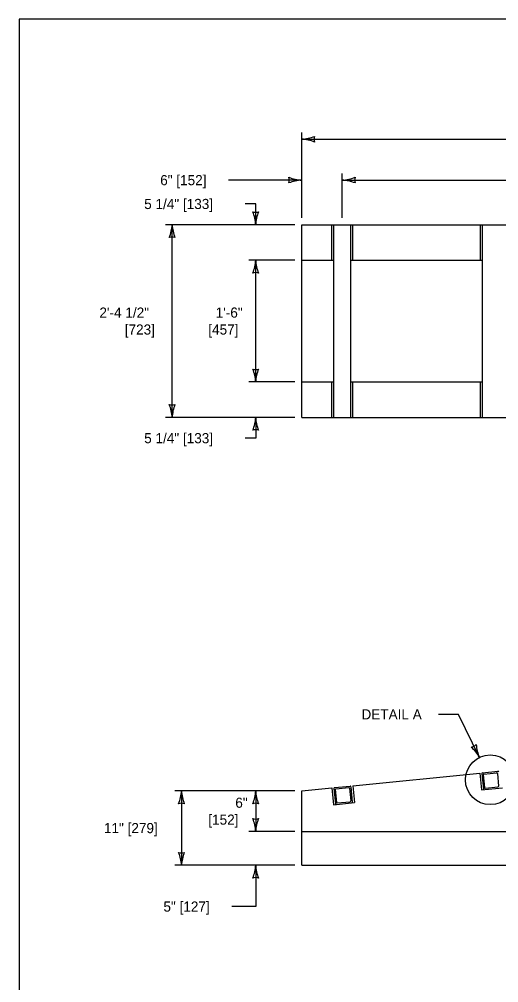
# Model space of a CAD drawing. Extents: x 49991.4 to 50021, y 49987.6 to 50011.4.
# Drawn here: x 50000.34 to 50003.17, y 50005.56 to 50011.26 of the extents above; entities that cross this region are included whole.
import ezdxf

# ---------------------------------------------------------------- set-up
doc = ezdxf.new("R2010")
doc.units = 0
for name, color, linetype in [('Level 1', 7, 'Continuous'), ('Level 2', 7, 'Continuous'), ('Level 3', 7, 'Continuous'), ('Level 4', 7, 'Continuous')]:
    doc.layers.add(name, color=color, linetype=linetype)

msp = doc.modelspace()

# ---------------------------------------------------------------- linework, layer by layer
at = {"layer": 'Level 1'}
for p, q in [((50002.0071, 50008.9073), (50002.0071, 50010.0473)), ((50002.0071, 50010.0473), (50006.5671, 50010.0473)), ((50002.1851, 50009.8374), (50002.1851, 50010.0473)), ((50002.1971, 50008.9073), (50002.1971, 50010.0473)), ((50002.2971, 50008.9073), (50002.2971, 50010.0473)), ((50002.3091, 50009.8374), (50002.3091, 50010.0473)), ((50003.0651, 50009.8374), (50003.0651, 50010.0473)), ((50003.0771, 50008.9073), (50003.0771, 50010.0473)), ((50002.0071, 50009.8374), (50002.1971, 50009.8374)), ((50002.2971, 50009.8374), (50003.0771, 50009.8374)), ((50002.0071, 50009.1174), (50002.1971, 50009.1174)), ((50002.1851, 50008.9073), (50002.1851, 50009.1174)), ((50002.2971, 50009.1174), (50003.0771, 50009.1174)), ((50002.3091, 50008.9073), (50002.3091, 50009.1174)), ((50003.0651, 50008.9073), (50003.0651, 50009.1174)), ((50002.0071, 50008.9073), (50006.5671, 50008.9073)), ((50002.3091, 50006.7277), (50003.0608, 50006.8028)), ((50003.0608, 50006.8028), (50003.0707, 50006.7032)), ((50003.0732, 50006.8), (50003.0823, 50006.7084)), ((50003.0768, 50006.8044), (50003.1688, 50006.8135)), ((50003.0812, 50006.7927), (50003.0887, 50006.7171)), ((50003.0848, 50006.7971), (50003.1608, 50006.8047)), ((50003.1652, 50006.8011), (50003.1727, 50006.7255)), ((50002.0071, 50006.6976), (50002.1851, 50006.7153)), ((50002.1851, 50006.7153), (50002.1951, 50006.6159)), ((50002.2011, 50006.7169), (50002.2932, 50006.7261)), ((50002.2091, 50006.7097), (50002.2852, 50006.7173)), ((50002.2975, 50006.7225), (50002.3066, 50006.631)), ((50002.3091, 50006.7277), (50002.3191, 50006.6282)), ((50003.0707, 50006.7032), (50003.1947, 50006.7156)), ((50003.0931, 50006.7135), (50003.1692, 50006.7211)), ((50002.0071, 50006.2576), (50002.0071, 50006.6976)), ((50002.1975, 50006.7126), (50002.2067, 50006.621)), ((50002.2055, 50006.7053), (50002.2131, 50006.6297)), ((50002.2895, 50006.7137), (50002.2971, 50006.6381)), ((50002.1951, 50006.6159), (50002.3191, 50006.6282)), ((50002.2174, 50006.6261), (50002.2935, 50006.6337)), ((50002.0071, 50006.2576), (50006.5671, 50006.2576))]:
    msp.add_line(p, q, dxfattribs=at)
msp.add_lwpolyline([(50008.6146, 50011.2628), (50000.3356, 50011.2628), (50000.3356, 50000.0624), (50008.6146, 50000.0624)], close=True, dxfattribs=at)
for centre, radius, start, end in [((50003.0772, 50006.8004), 0.00402, 95.7106, 185.7106), ((50003.0852, 50006.7931), 0.00402, 95.7106, 185.7106), ((50003.1612, 50006.8007), 0.00402, 5.7106, 95.7106), ((50003.1692, 50006.8096), 0.00398, 6.4993, 96.4993), ((50002.2015, 50006.7129), 0.00397, 95.0636, 185.0636), ((50002.2855, 50006.7133), 0.00397, 5.0636, 95.0636), ((50002.2935, 50006.7221), 0.00397, 5.0636, 95.0636), ((50003.0927, 50006.7175), 0.00402, 185.7106, 275.7106), ((50003.1687, 50006.7251), 0.00398, 276.4993, 6.4993), ((50002.2095, 50006.7057), 0.00402, 95.7106, 185.7106), ((50003.0863, 50006.7088), 0.00402, 185.9049, 275.9049), ((50002.2104, 50006.6211), 0.00368, 181.6745, 271.6745), ((50002.217, 50006.63), 0.00397, 185.0636, 275.0636), ((50002.2931, 50006.6377), 0.00402, 275.7106, 5.7106), ((50002.3027, 50006.6305), 0.00396, 276.2831, 6.3172)]:
    msp.add_arc(centre, radius, start, end, dxfattribs=at)
at = {"layer": 'Level 3'}
for p, q in [((50002.0071, 50010.0873), (50002.0071, 50010.5932)), ((50002.0071, 50010.5532), (50006.5671, 50010.5532)), ((50002.0071, 50010.311), (50001.5747, 50010.311)), ((50002.2471, 50010.0873), (50002.2471, 50010.351)), ((50002.2471, 50010.311), (50005.7671, 50010.311)), ((50001.9671, 50010.0473), (50001.2004, 50010.0473)), ((50001.2404, 50008.9073), (50001.2404, 50010.0473)), ((50001.9671, 50009.8374), (50001.6948, 50009.8374)), ((50001.7348, 50009.1174), (50001.7348, 50009.8374)), ((50001.9671, 50009.1174), (50001.6948, 50009.1174)), ((50001.9671, 50008.9073), (50001.2004, 50008.9073)), ((50002.9345, 50007.1503), (50002.8175, 50007.1503)), ((50003.0588, 50006.8956), (50002.9345, 50007.1503)), ((50001.9671, 50006.6976), (50001.2557, 50006.6976)), ((50001.2957, 50006.6976), (50001.2957, 50006.2576)), ((50001.7348, 50006.6976), (50001.7348, 50006.4576)), ((50001.9671, 50006.4576), (50001.6948, 50006.4576)), ((50001.9671, 50006.2576), (50001.2557, 50006.2576)), ((50001.7348, 50006.2576), (50001.7348, 50006.0132)), ((50001.7348, 50006.0132), (50001.5937, 50006.0132))]:
    msp.add_line(p, q, dxfattribs=at)
for points in [[(50001.7348, 50010.0473), (50001.7348, 50010.1701), (50001.6734, 50010.1701)], [(50001.7348, 50008.9073), (50001.7348, 50008.7845), (50001.6734, 50008.7845)]]:
    msp.add_lwpolyline(points, dxfattribs=at)
msp.add_circle((50003.1234, 50006.7633), 0.1472, dxfattribs=at)
for centre, radius, start, end in [((50001.9956, 50010.7859), 0.233, 272.8273, 292.0772), ((50001.9979, 50010.3311), 0.2223, 67.456, 87.6395), ((50002.1353, 50010.5532), 0.0548, 162.1388, 197.8612), ((50002.0163, 50010.5331), 0.2223, 247.456, 267.6395), ((50001.8789, 50010.311), 0.0548, 342.1388, 17.8612), ((50002.0186, 50010.0783), 0.233, 92.8273, 112.0772), ((50002.2356, 50010.5437), 0.233, 272.8273, 292.0772), ((50002.2379, 50010.0889), 0.2223, 67.456, 87.6395), ((50002.3753, 50010.311), 0.0548, 162.1388, 197.8612), ((50001.7348, 50010.1755), 0.0548, 252.1388, 287.8612), ((50001.5021, 50010.0358), 0.233, 2.8273, 22.0772), ((50001.9569, 50010.0381), 0.2223, 157.456, 177.6395), ((50001.0183, 50010.0565), 0.2223, 337.456, 357.6395), ((50001.4731, 50010.0588), 0.233, 182.8273, 202.0772), ((50001.2404, 50009.9191), 0.0548, 72.1388, 107.8612), ((50001.5021, 50009.8489), 0.233, 337.9228, 357.1727), ((50001.9569, 50009.8466), 0.2223, 182.3605, 202.544), ((50001.7348, 50009.7092), 0.0548, 72.1388, 107.8612), ((50001.7348, 50009.2456), 0.0548, 252.1388, 287.8612), ((50001.5021, 50009.1059), 0.233, 2.8273, 22.0772), ((50001.9569, 50009.1082), 0.2223, 157.456, 177.6395), ((50001.2404, 50009.0355), 0.0548, 252.1388, 287.8612), ((50001.0077, 50008.8958), 0.233, 2.8273, 22.0772), ((50001.4625, 50008.8981), 0.2223, 157.456, 177.6395), ((50001.5021, 50008.9188), 0.233, 337.9228, 357.1727), ((50001.9569, 50008.9165), 0.2223, 182.3605, 202.544), ((50001.7348, 50008.7791), 0.0548, 72.1388, 107.8612), ((50003.0022, 50007.0106), 0.0548, 278.329, 314.0514), ((50002.8551, 50006.7826), 0.233, 29.0175, 48.2674), ((50003.2622, 50006.9854), 0.2223, 183.6462, 203.8297), ((50001.0735, 50006.7068), 0.2223, 337.456, 357.6395), ((50001.5284, 50006.7091), 0.233, 182.8273, 202.0772), ((50001.5127, 50006.7068), 0.2223, 337.456, 357.6395), ((50001.9675, 50006.7091), 0.233, 182.8273, 202.0772), ((50001.2957, 50006.5694), 0.0548, 72.1388, 107.8612), ((50001.7348, 50006.5694), 0.0548, 72.1388, 107.8612), ((50001.7348, 50006.5858), 0.0548, 252.1388, 287.8612), ((50001.5021, 50006.4461), 0.233, 2.8273, 22.0772), ((50001.9569, 50006.4484), 0.2223, 157.456, 177.6395), ((50001.2957, 50006.3858), 0.0548, 252.1388, 287.8612), ((50001.0629, 50006.2461), 0.233, 2.8273, 22.0772), ((50001.5178, 50006.2484), 0.2223, 157.456, 177.6395), ((50001.5127, 50006.2668), 0.2223, 337.456, 357.6395), ((50001.9675, 50006.2691), 0.233, 182.8273, 202.0772), ((50001.7348, 50006.1294), 0.0548, 72.1388, 107.8612)]:
    msp.add_arc(centre, radius, start, end, dxfattribs=at)
at = {"layer": 'Level 4'}
msp.add_line((50002.0071, 50006.4576), (50006.5671, 50006.4576), dxfattribs=at)

# ---------------------------------------------------------------- texts
at = {"layer": 'Level 2'}
for s, p in [('6" [152]', (50001.1697, 50010.281)), ('5 1/4" [133]', (50001.075, 50010.1401)), ('2\'-4 1/2"', (50000.81, 50009.4973)), ('1\'-6"', (50001.4979, 50009.4974)), ('[723]', (50000.96, 50009.3973)), ('[457]', (50001.4544, 50009.3974)), ('5 1/4" [133]', (50001.075, 50008.7545)), ('DETAIL A', (50002.3609, 50007.1203)), ('6"', (50001.6141, 50006.5976)), ('[152]', (50001.4544, 50006.4976)), ('11" [279]', (50000.8368, 50006.4476)), ('5" [127]', (50001.1888, 50005.9832))]:
    msp.add_text(s, height=0.06, dxfattribs=at).set_placement(p)

doc.saveas('drawing.dxf')
